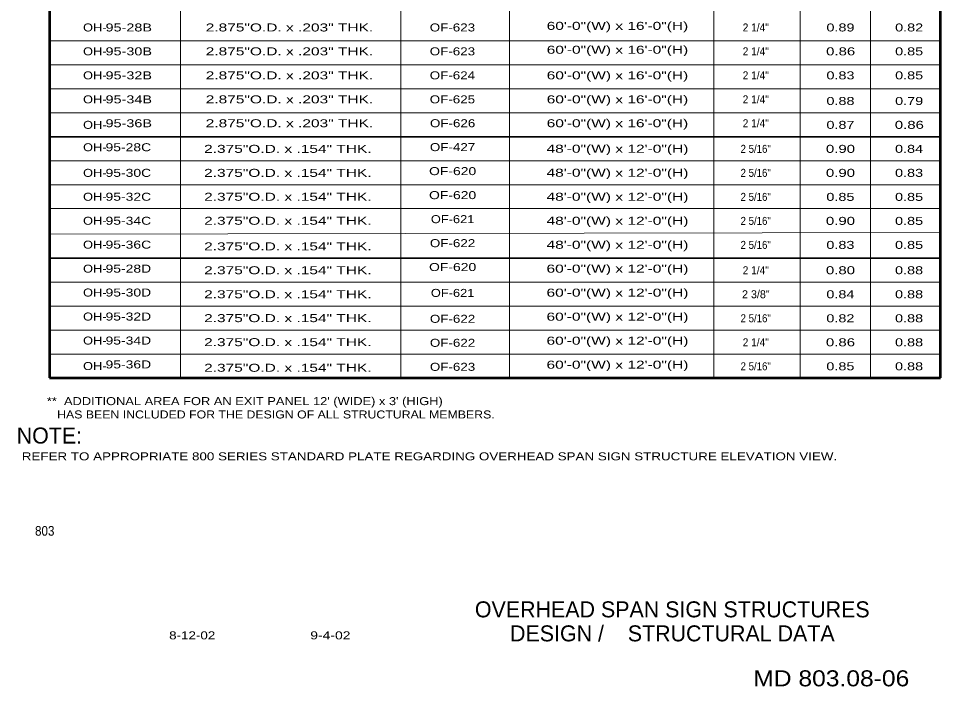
# Model space of a CAD drawing. Extents: x -34810.3 to -34803.4, y -181503.6 to -181493.6.
# Drawn here: x -34810.3 to -34803.39, y -181503.6 to -181498.59 of the extents above; entities that cross this region are included whole.
import ezdxf
from ezdxf.enums import TextEntityAlignment as Align

# ---------------------------------------------------------------- set-up
doc = ezdxf.new("R2010")
doc.units = 0
doc.header["$LTSCALE"] = 0.024
doc.layers.add('1', color=7, linetype='Continuous', lineweight=13)
doc.layers.add('13', color=7, linetype='Continuous', lineweight=25)
doc.layers.add('12', color=7, linetype='Continuous')

msp = doc.modelspace()

# ---------------------------------------------------------------- linework, layer by layer
at = {"layer": '1', "lineweight": 53}
for p, q in [((-34810.067, -181493.589), (-34810.067, -181501.286)), ((-34803.387, -181501.286), (-34803.387, -181493.589)), ((-34810.067, -181501.286), (-34803.387, -181501.286))]:
    msp.add_line(p, q, dxfattribs=at)
at = {"layer": '1'}
for p, q in [((-34809.085, -181493.589), (-34809.085, -181501.286)), ((-34809.085, -181493.589), (-34809.085, -181501.286)), ((-34807.433, -181493.589), (-34807.433, -181501.286)), ((-34806.619, -181493.589), (-34806.619, -181501.286)), ((-34805.087, -181493.589), (-34805.087, -181501.286)), ((-34804.44, -181501.286), (-34804.44, -181493.589)), ((-34803.913, -181493.84), (-34803.913, -181501.286)), ((-34803.387, -181498.76), (-34810.067, -181498.76)), ((-34803.387, -181498.94), (-34810.067, -181498.94)), ((-34803.387, -181499.12), (-34810.067, -181499.12)), ((-34803.387, -181499.299), (-34810.067, -181499.299)), ((-34803.387, -181499.658), (-34810.067, -181499.658)), ((-34803.387, -181499.838), (-34810.067, -181499.838)), ((-34803.387, -181500.017), (-34810.067, -181500.017)), ((-34803.387, -181500.197), (-34810.067, -181500.209)), ((-34803.387, -181500.568), (-34810.067, -181500.568)), ((-34803.387, -181500.748), (-34810.067, -181500.748)), ((-34803.387, -181500.927), (-34810.067, -181500.927)), ((-34803.387, -181501.107), (-34810.067, -181501.107))]:
    msp.add_line(p, q, dxfattribs=at)
at = {"layer": '1', "lineweight": 35}
for p, q in [((-34803.387, -181499.479), (-34810.067, -181499.479)), ((-34803.387, -181500.389), (-34810.067, -181500.389))]:
    msp.add_line(p, q, dxfattribs=at)

# ---------------------------------------------------------------- texts
at = {"layer": '12'}
msp.add_text('NOTE:', height=0.12, dxfattribs=at).set_placement((-34810.069, -181501.778), align=Align.CENTER)
at = {"layer": '13'}
for s, height, width, p in [('OH-', 0.05983, 1.2, (-34809.7285, -181498.689)), ('2.875"O.D. x .203" THK.', 0.05983, 1.45, (-34808.269, -181498.689)), ('OF-623', 0.06, 1.25, (-34807.047, -181498.689)), ('60\'-0"(W) x 16\'-0"(H)', 0.05983, 1.45, (-34805.8095, -181498.677)), ('2 1/4"', 0.05983, 0.95, (-34804.7725, -181498.689)), ('0.89', 0.05983, 1.35, (-34804.1375, -181498.689)), ('0.82', 0.05983, 1.35, (-34803.6225, -181498.689)), ('OH-', 0.05983, 1.2, (-34809.7285, -181498.868)), ('2.875"O.D. x .203" THK.', 0.05983, 1.45, (-34808.269, -181498.868)), ('OF-623', 0.06, 1.25, (-34807.047, -181498.868)), ('60\'-0"(W) x 16\'-0"(H)', 0.05983, 1.45, (-34805.8095, -181498.856)), ('2 1/4"', 0.05983, 0.95, (-34804.7725, -181498.868)), ('0.86', 0.05983, 1.4, (-34804.136, -181498.868)), ('0.85', 0.05983, 1.35, (-34803.6225, -181498.868)), ('OH-', 0.05983, 1.2, (-34809.7285, -181499.048)), ('2.875"O.D. x .203" THK.', 0.05983, 1.45, (-34808.269, -181499.048)), ('OF-624', 0.06, 1.25, (-34807.047, -181499.048)), ('60\'-0"(W) x 16\'-0"(H)', 0.05983, 1.45, (-34805.8095, -181499.048)), ('2 1/4"', 0.05983, 0.95, (-34804.7725, -181499.048)), ('0.83', 0.05983, 1.35, (-34804.1375, -181499.048)), ('0.85', 0.05983, 1.35, (-34803.6225, -181499.048)), ('OH-', 0.05983, 1.2, (-34809.7285, -181499.228)), ('2.875"O.D. x .203" THK.', 0.05983, 1.45, (-34808.269, -181499.228)), ('OF-625', 0.06, 1.25, (-34807.047, -181499.228)), ('60\'-0"(W) x 16\'-0"(H)', 0.05983, 1.45, (-34805.8095, -181499.228)), ('2 1/4"', 0.05983, 0.95, (-34804.7725, -181499.228)), ('0.88', 0.05983, 1.35, (-34804.1375, -181499.24)), ('0.79', 0.05983, 1.35, (-34803.6225, -181499.24)), ('OH-', 0.05983, 1.2, (-34809.7285, -181499.419)), ('2.875"O.D. x .203" THK.', 0.05983, 1.45, (-34808.269, -181499.407)), ('OF-626', 0.06, 1.25, (-34807.0455, -181499.407)), ('60\'-0"(W) x 16\'-0"(H)', 0.05983, 1.45, (-34805.8095, -181499.407)), ('2 1/4"', 0.05983, 0.95, (-34804.7725, -181499.407)), ('0.87', 0.05983, 1.35, (-34804.1375, -181499.419)), ('0.86', 0.05983, 1.4, (-34803.621, -181499.419)), ('OH-', 0.05983, 1.2, (-34809.7285, -181499.587)), ('OF-427', 0.06, 1.25, (-34807.046, -181499.586)), ('2.375"O.D. x .154" THK.', 0.05983, 1.45, (-34808.281, -181499.599)), ('48\'-0"(W) x 12\'-0"(H)', 0.06, 1.45, (-34805.8095, -181499.598)), ('2 5/16"', 0.06, 0.9, (-34804.773, -181499.599)), ('0.90', 0.06, 1.4, (-34804.1375, -181499.599)), ('0.84', 0.06, 1.35, (-34803.623, -181499.599)), ('OH-', 0.05983, 1.2, (-34809.7285, -181499.779)), ('2.375"O.D. x .154" THK.', 0.05983, 1.45, (-34808.281, -181499.779)), ('OF-620', 0.06, 1.3, (-34807.0455, -181499.766)), ('48\'-0"(W) x 12\'-0"(H)', 0.06, 1.45, (-34805.8095, -181499.778)), ('2 5/16"', 0.06, 0.9, (-34804.773, -181499.779)), ('0.90', 0.06, 1.4, (-34804.1375, -181499.779)), ('0.83', 0.06, 1.35, (-34803.623, -181499.779)), ('OH-', 0.05983, 1.2, (-34809.7285, -181499.958)), ('2.375"O.D. x .154" THK.', 0.05983, 1.45, (-34808.281, -181499.958)), ('OF-620', 0.06, 1.3, (-34807.0455, -181499.946)), ('48\'-0"(W) x 12\'-0"(H)', 0.06, 1.45, (-34805.8095, -181499.958)), ('2 5/16"', 0.06, 0.9, (-34804.773, -181499.959)), ('0.85', 0.06, 1.35, (-34804.138, -181499.959)), ('0.85', 0.06, 1.35, (-34803.623, -181499.959)), ('OH-', 0.05983, 1.2, (-34809.7285, -181500.138)), ('2.375"O.D. x .154" THK.', 0.05983, 1.45, (-34808.281, -181500.138)), ('OF-621', 0.06, 1.2, (-34807.0455, -181500.126)), ('48\'-0"(W) x 12\'-0"(H)', 0.06, 1.45, (-34805.8095, -181500.138)), ('2 5/16"', 0.06, 0.9, (-34804.773, -181500.139)), ('0.90', 0.06, 1.4, (-34804.1375, -181500.139)), ('0.85', 0.06, 1.35, (-34803.623, -181500.139)), ('OH-', 0.05983, 1.2, (-34809.7285, -181500.317)), ('2.375"O.D. x .154" THK.', 0.05983, 1.45, (-34808.281, -181500.33)), ('OF-622', 0.06, 1.25, (-34807.046, -181500.306)), ('48\'-0"(W) x 12\'-0"(H)', 0.06, 1.45, (-34805.8095, -181500.318)), ('2 5/16"', 0.06, 0.9, (-34804.773, -181500.319)), ('0.83', 0.06, 1.35, (-34804.138, -181500.319)), ('0.85', 0.06, 1.35, (-34803.623, -181500.319)), ('OF-620', 0.06, 1.3, (-34807.0455, -181500.485)), ('OH-', 0.05983, 1.2, (-34809.7285, -181500.497)), ('2.375"O.D. x .154" THK.', 0.05983, 1.45, (-34808.281, -181500.509)), ('60\'-0"(W) x 12\'-0"(H)', 0.06, 1.45, (-34805.8095, -181500.497)), ('2 1/4"', 0.05983, 0.95, (-34804.7725, -181500.509)), ('0.80', 0.06, 1.4, (-34804.1375, -181500.509)), ('0.88', 0.06, 1.35, (-34803.623, -181500.509)), ('OH-', 0.05983, 1.2, (-34809.7285, -181500.676)), ('2.375"O.D. x .154" THK.', 0.05983, 1.45, (-34808.281, -181500.689)), ('OF-621', 0.06, 1.2, (-34807.0455, -181500.679)), ('60\'-0"(W) x 12\'-0"(H)', 0.06, 1.45, (-34805.8095, -181500.677)), ('0.84', 0.06, 1.35, (-34804.138, -181500.689)), ('0.88', 0.06, 1.35, (-34803.623, -181500.689)), ('OH-', 0.05983, 1.2, (-34809.7285, -181500.856)), ('2.375"O.D. x .154" THK.', 0.05983, 1.45, (-34808.281, -181500.868)), ('OF-622', 0.06, 1.25, (-34807.046, -181500.873)), ('60\'-0"(W) x 12\'-0"(H)', 0.06, 1.45, (-34805.8095, -181500.857)), ('2 5/16"', 0.06, 0.9, (-34804.773, -181500.869)), ('0.82', 0.06, 1.35, (-34804.138, -181500.869)), ('0.88', 0.06, 1.35, (-34803.623, -181500.869)), ('OH-', 0.05983, 1.2, (-34809.7285, -181501.036)), ('60\'-0"(W) x 12\'-0"(H)', 0.06, 1.45, (-34805.8095, -181501.037)), ('2.375"O.D. x .154" THK.', 0.05983, 1.45, (-34808.281, -181501.048)), ('OF-622', 0.06, 1.25, (-34807.046, -181501.053)), ('2 1/4"', 0.05983, 0.95, (-34804.7725, -181501.049)), ('0.86', 0.06, 1.4, (-34804.1375, -181501.049)), ('0.88', 0.06, 1.35, (-34803.623, -181501.049)), ('OH-', 0.05983, 1.2, (-34809.7285, -181501.227)), ('2.375"O.D. x .154" THK.', 0.05983, 1.45, (-34808.281, -181501.24)), ('OF-623', 0.06, 1.25, (-34807.046, -181501.233)), ('60\'-0"(W) x 12\'-0"(H)', 0.06, 1.45, (-34805.8095, -181501.217)), ('2 5/16"', 0.06, 0.9, (-34804.773, -181501.229)), ('0.85', 0.06, 1.35, (-34804.138, -181501.229)), ('0.88', 0.06, 1.35, (-34803.623, -181501.229)), ('REFER TO APPROPRIATE 800 SERIES STANDARD PLATE REGARDING OVERHEAD SPAN SIGN STRUCTURE ELEVATION VIEW.', 0.06, 1.25, (-34807.219, -181501.904)), ('803', 0.07251, 0.9, (-34810.104, -181502.469))]:
    msp.add_text(s, height=height, dxfattribs=dict(at, width=width)).set_placement(p, align=Align.CENTER)
for s, height, width, p in [('95-28B', 0.05983, 1.35, (-34809.648, -181498.689)), ('95-30B', 0.05983, 1.35, (-34809.648, -181498.868)), ('95-32B', 0.05983, 1.35, (-34809.648, -181499.048)), ('95-34B', 0.05983, 1.35, (-34809.648, -181499.228)), ('95-36B', 0.05983, 1.35, (-34809.648, -181499.407)), ('95-28C', 0.06, 1.3, (-34809.648, -181499.587)), ('95-30C', 0.06, 1.3, (-34809.648, -181499.779)), ('95-32C', 0.06, 1.3, (-34809.648, -181499.958)), ('95-34C', 0.06, 1.3, (-34809.648, -181500.138)), ('95-36C', 0.06, 1.3, (-34809.648, -181500.317)), ('95-28D', 0.06, 1.3, (-34809.648, -181500.497)), ('95-30D', 0.06, 1.3, (-34809.648, -181500.676)), ('95-32D', 0.06, 1.3, (-34809.648, -181500.856)), ('95-34D', 0.06, 1.3, (-34809.648, -181501.036)), ('95-36D', 0.06, 1.3, (-34809.648, -181501.215)), ("**  ADDITIONAL AREA FOR AN EXIT PANEL 12' (WIDE) x 3' (HIGH)", 0.06, 1.2, (-34810.088, -181501.49)), ('   HAS BEEN INCLUDED FOR THE DESIGN OF ALL STRUCTURAL MEMBERS.', 0.06, 1.15, (-34810.088, -181501.59)), ('8-12-02', 0.06, 1.25, (-34809.171, -181503.246)), ('9-4-02', 0.06, 1.3, (-34808.113, -181503.246)), ('MD 803.08-06', 0.12, 1.15, (-34804.791, -181503.598))]:
    msp.add_text(s, height=height, dxfattribs=dict(at, width=width)).set_placement(p)
for s, height, p in [('2 3/8"', 0.06, (-34804.772, -181500.689)), ('OVERHEAD SPAN SIGN STRUCTURES', 0.12, (-34805.3985, -181503.081)), ('DESIGN /    STRUCTURAL DATA', 0.12, (-34805.398, -181503.261))]:
    msp.add_text(s, height=height, dxfattribs=at).set_placement(p, align=Align.CENTER)

doc.saveas('drawing.dxf')
